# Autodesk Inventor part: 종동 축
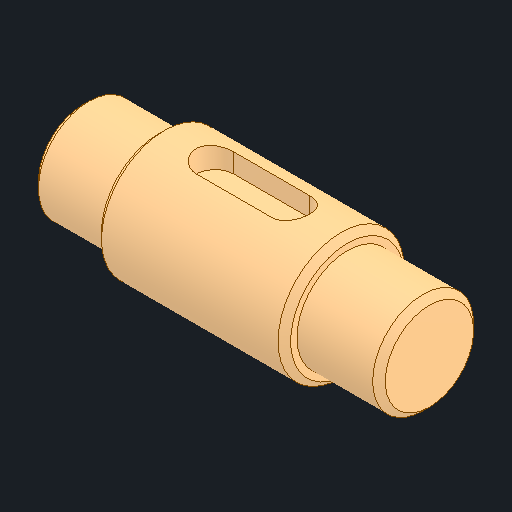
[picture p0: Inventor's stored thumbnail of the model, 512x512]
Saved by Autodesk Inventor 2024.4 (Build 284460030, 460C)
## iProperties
Created: 2026-09
Part Number: 종동 축
Material: 강철, 탄소
Document SubType Name: Modeling
Designer: user
Density: 7.85 g/cm^3
Appearance: 기본값
Author: jhkim
Sending System: Autodesk Inventor 2027
Preprocessor: ST-DEVELOPER v20.1
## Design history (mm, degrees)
feature "솔리드1"
node "솔리드2"
